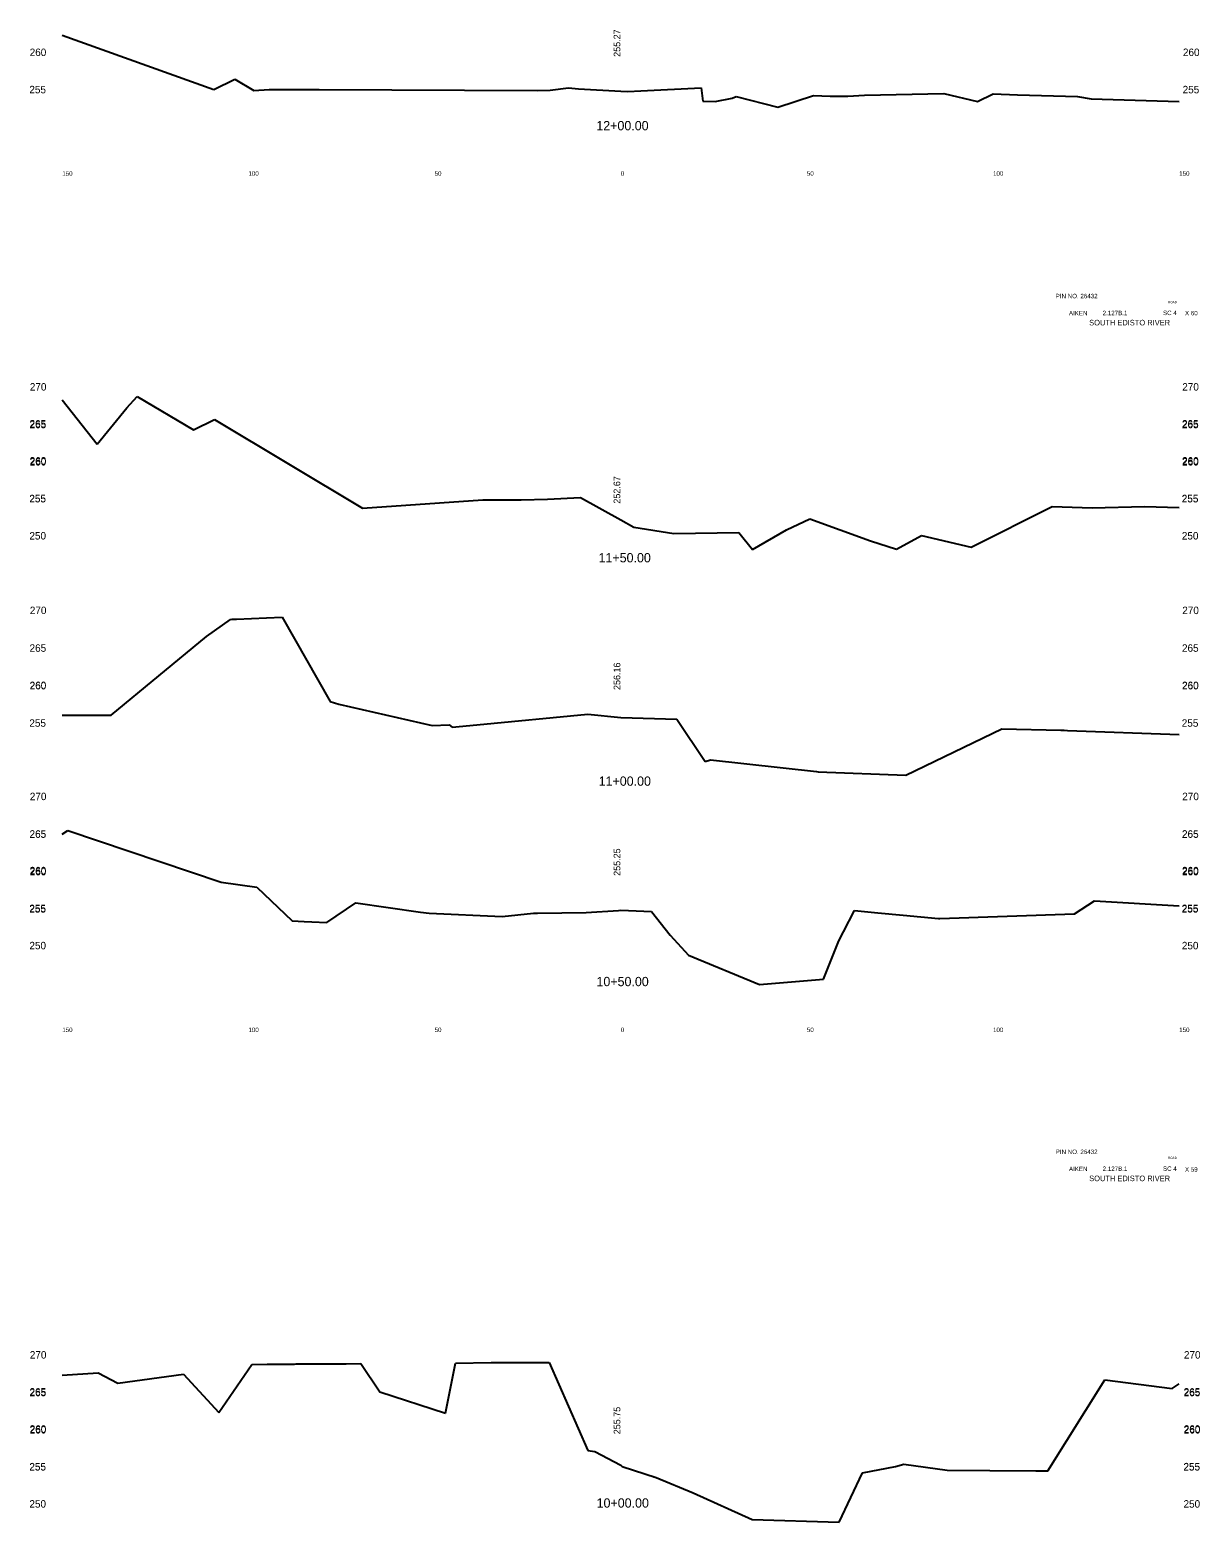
# Model space of a CAD drawing. Extents: x 557 to 872, y 628 to 2216.
# Drawn here: x 557.8 to 872.2, y 1426.2 to 1827 of the extents above; entities that cross this region are included whole.
import ezdxf

# ---------------------------------------------------------------- set-up
doc = ezdxf.new("R2010")
doc.units = 0
for name, color, linetype in [('Level 1', 7, 'Continuous'), ('Level 10', 7, 'Continuous'), ('Level 13', 7, 'Continuous'), ('Level 3', 7, 'Continuous'), ('Level 60', 7, 'Continuous')]:
    doc.layers.add(name, color=color, linetype=linetype)

msp = doc.modelspace()

# ---------------------------------------------------------------- linework, layer by layer
at = {"layer": 'Level 60'}
for p, q in [((566.54, 1825.54), (607.23, 1810.95)), ((607.23, 1810.95), (612.84, 1813.76)), ((612.84, 1813.76), (617.95, 1810.7)), ((617.95, 1810.7), (622.1, 1810.99)), ((622.1, 1810.99), (635.53, 1810.96)), ((635.53, 1810.96), (694.09, 1810.69)), ((694.09, 1810.69), (697.55, 1810.81)), ((697.55, 1810.81), (702.52, 1811.44)), ((702.52, 1811.44), (705.21, 1811.16)), ((705.21, 1811.16), (716.54, 1810.55)), ((716.54, 1810.55), (718.47, 1810.44)), ((718.47, 1810.44), (721.9, 1810.57)), ((721.9, 1810.57), (738.11, 1811.4)), ((738.11, 1811.4), (738.59, 1807.82)), ((738.59, 1807.82), (741.89, 1807.7)), ((741.89, 1807.7), (746.47, 1808.64)), ((746.47, 1808.64), (747.56, 1809.06)), ((747.56, 1809.06), (758.71, 1806.2)), ((758.71, 1806.2), (768.31, 1809.34)), ((768.31, 1809.34), (772.82, 1809.14)), ((772.82, 1809.14), (777.52, 1809.14)), ((777.52, 1809.14), (782.05, 1809.46)), ((782.05, 1809.46), (803.35, 1809.88)), ((803.35, 1809.88), (812.35, 1807.77)), ((812.35, 1807.77), (816.59, 1809.81)), ((816.59, 1809.81), (823.11, 1809.54)), ((823.11, 1809.54), (839.22, 1809.07)), ((839.22, 1809.07), (842.87, 1808.44)), ((842.87, 1808.44), (866.54, 1807.73)), ((566.54, 1727.6), (575.88, 1715.67)), ((583.88, 1725.47), (586.62, 1728.46)), ((586.62, 1728.46), (601.82, 1719.56)), ((575.88, 1715.67), (583.88, 1725.47)), ((601.82, 1719.56), (607.39, 1722.35)), ((607.39, 1722.35), (647.2, 1698.52)), ((647.2, 1698.52), (679.53, 1700.78)), ((679.53, 1700.78), (681.44, 1700.77)), ((681.44, 1700.77), (689.78, 1700.73)), ((689.78, 1700.73), (696.88, 1700.97)), ((696.88, 1700.97), (705.72, 1701.34)), ((705.72, 1701.34), (716.54, 1695.34)), ((761.07, 1692.69), (767.33, 1695.61)), ((767.33, 1695.61), (783.64, 1689.76)), ((810.64, 1688.07), (832.45, 1698.95)), ((832.45, 1698.95), (843.18, 1698.62)), ((843.18, 1698.62), (857.19, 1698.98)), ((857.19, 1698.98), (866.54, 1698.7)), ((716.54, 1695.34), (720.09, 1693.37)), ((720.09, 1693.37), (730.76, 1691.69)), ((730.76, 1691.69), (748.3, 1691.93)), ((748.3, 1691.93), (751.94, 1687.43)), ((751.94, 1687.43), (761.07, 1692.69)), ((783.64, 1689.76), (790.62, 1687.5)), ((790.62, 1687.5), (797.33, 1691.17)), ((797.33, 1691.17), (810.64, 1688.07)), ((605.24, 1664.07), (611.69, 1668.61)), ((611.69, 1668.61), (612.14, 1668.69)), ((612.14, 1668.69), (613.33, 1668.69)), ((613.33, 1668.69), (621.42, 1669.05)), ((621.42, 1669.05), (625.63, 1669.21)), ((625.63, 1669.21), (638.49, 1646.61)), ((579.62, 1642.92), (605.24, 1664.07)), ((638.49, 1646.61), (640.77, 1645.9)), ((640.77, 1645.9), (665.85, 1640.12)), ((566.54, 1642.87), (579.62, 1642.92)), ((665.85, 1640.12), (670.42, 1640.34)), ((670.42, 1640.34), (671.26, 1639.65)), ((671.26, 1639.65), (677.89, 1640.29)), ((677.89, 1640.29), (707.74, 1643.14)), ((707.74, 1643.14), (716.54, 1642.31)), ((716.54, 1642.31), (731.6, 1641.84)), ((731.6, 1641.84), (739.17, 1630.44)), ((793.13, 1626.81), (818.87, 1639.24)), ((818.87, 1639.24), (834.73, 1638.88)), ((834.73, 1638.88), (835.62, 1638.88)), ((835.62, 1638.88), (836.57, 1638.8)), ((836.57, 1638.8), (866.54, 1637.74)), ((739.17, 1630.44), (740.69, 1630.88)), ((740.69, 1630.88), (769.15, 1627.74)), ((769.15, 1627.74), (769.56, 1627.72)), ((769.56, 1627.72), (793.13, 1626.81)), ((566.54, 1610.96), (568.01, 1611.92)), ((568.01, 1611.92), (609.22, 1598.09)), ((609.22, 1598.09), (618.75, 1596.75)), ((618.75, 1596.75), (628.25, 1587.63)), ((637.6, 1587.24), (645.36, 1592.47)), ((645.36, 1592.47), (662.71, 1590.04)), ((838.4, 1589.53), (843.77, 1593.08)), ((843.77, 1593.08), (866.54, 1591.71)), ((628.25, 1587.63), (631.49, 1587.45)), ((631.49, 1587.45), (633.55, 1587.44)), ((633.55, 1587.44), (637.6, 1587.24)), ((662.71, 1590.04), (665.06, 1589.69)), ((665.06, 1589.69), (684.73, 1588.8)), ((684.73, 1588.8), (693.06, 1589.74)), ((693.06, 1589.74), (694.22, 1589.77)), ((694.22, 1589.77), (707.28, 1589.94)), ((707.28, 1589.94), (715.97, 1590.46)), ((715.97, 1590.46), (716.58, 1590.5)), ((716.58, 1590.5), (724.84, 1590.2)), ((724.84, 1590.2), (729.83, 1583.86)), ((776.36, 1584.74), (779.35, 1590.42)), ((779.35, 1590.42), (785.61, 1589.81)), ((785.61, 1589.81), (792.38, 1589.17)), ((792.38, 1589.17), (801.92, 1588.3)), ((801.92, 1588.3), (802.29, 1588.31)), ((802.29, 1588.31), (838.4, 1589.53)), ((729.83, 1583.86), (734.72, 1578.48)), ((775.09, 1582.29), (776.36, 1584.74)), ((770.99, 1571.98), (775.09, 1582.29)), ((734.72, 1578.48), (753.82, 1570.6)), ((753.82, 1570.6), (770.99, 1571.98)), ((608.54, 1455.64), (617.46, 1468.53)), ((617.46, 1468.53), (621.57, 1468.59)), ((621.57, 1468.59), (622.02, 1468.62)), ((622.02, 1468.62), (628.9, 1468.64)), ((628.9, 1468.64), (629.32, 1468.72)), ((629.32, 1468.72), (642.8, 1468.72)), ((642.8, 1468.72), (646.73, 1468.74)), ((646.73, 1468.74), (651.87, 1461.14)), ((669.49, 1455.46), (672.12, 1468.91)), ((672.12, 1468.91), (681.77, 1469.03)), ((681.77, 1469.03), (697.28, 1469.09)), ((697.28, 1469.09), (707.7, 1445.42)), ((566.54, 1465.61), (576.16, 1466.26)), ((576.16, 1466.26), (581.42, 1463.49)), ((581.42, 1463.49), (599.09, 1465.95)), ((599.09, 1465.95), (608.54, 1455.64)), ((831.3, 1439.95), (846.6, 1464.39)), ((846.6, 1464.39), (864.67, 1462.05)), ((864.67, 1462.05), (866.54, 1463.29)), ((651.87, 1461.14), (669.49, 1455.46)), ((707.7, 1445.42), (709.6, 1445.14)), ((709.6, 1445.14), (716.6, 1441.46)), ((716.6, 1441.46), (716.91, 1441.14)), ((716.91, 1441.14), (726.07, 1438.15)), ((775.23, 1426.17), (781.45, 1439.44)), ((781.45, 1439.44), (790.34, 1441.12)), ((790.34, 1441.12), (792.56, 1441.7)), ((792.56, 1441.7), (792.66, 1441.56)), ((792.56, 1441.7), (804.26, 1440.16)), ((804.26, 1440.16), (815.68, 1440.04)), ((815.68, 1440.04), (828.02, 1439.92)), ((828.02, 1439.92), (831.3, 1439.95)), ((725.46, 1438.38), (726.07, 1438.15)), ((726.07, 1438.15), (735.95, 1434.02)), ((735.95, 1434.02), (751.85, 1426.9)), ((751.85, 1426.9), (775.23, 1426.17))]:
    msp.add_line(p, q, dxfattribs=at)

# ---------------------------------------------------------------- texts
at = {"layer": 'Level 1'}
for s, height, p in [('12+00.00', 2.5, (709.98, 1800)), ('PIN NO. 26432', 1.2, (833.38, 1754.88)), ('SC 4', 1.2, (862.2, 1750.36)), ('ROAD', 0.6, (863.53, 1753.55)), ('AIKEN', 1.2, (836.93, 1750.29)), ('SOUTH EDISTO RIVER', 1.5, (842.36, 1747.59)), (' 2.127B.1', 1.2, (845.53, 1750.34)), ('X 60', 1.2, (868.1, 1750.3)), ('11+50.00', 2.5, (710.58, 1683.95)), ('11+00.00', 2.5, (710.61, 1623.95)), ('10+50.00', 2.5, (710.02, 1570.12)), ('PIN NO. 26432', 1.2, (833.38, 1525.04)), ('ROAD', 0.6, (863.53, 1523.71)), ('AIKEN', 1.2, (836.93, 1520.44)), ('SOUTH EDISTO RIVER', 1.5, (842.36, 1517.75)), (' 2.127B.1', 1.2, (845.53, 1520.49)), ('SC 4', 1.2, (862.2, 1520.51)), ('X 59', 1.2, (868.1, 1520.31)), ('10+00.00', 2.5, (710.06, 1430.07))]:
    msp.add_text(s, height=height, dxfattribs=at).set_placement(p)
at = {"layer": 'Level 10'}
for s, p in [('255.27', (716.43, 1819.74)), ('252.67', (716.41, 1699.73)), ('256.16', (716.43, 1649.68)), ('255.25', (716.43, 1599.76)), ('255.75', (716.43, 1449.78))]:
    msp.add_text(s, height=1.8, rotation=90, dxfattribs=at).set_placement(p)
at = {"layer": 'Level 13'}
for s, p in [('150', (566.54, 1787.8)), ('100', (616.54, 1787.8)), ('50', (666.54, 1787.8)), ('0', (716.54, 1787.8)), ('50', (766.54, 1787.8)), ('100', (816.54, 1787.8)), ('150', (866.54, 1787.8)), ('150', (566.54, 1557.8)), ('100', (616.54, 1557.8)), ('50', (666.54, 1557.8)), ('0', (716.54, 1557.8)), ('50', (766.54, 1557.8)), ('100', (816.54, 1557.8)), ('150', (866.54, 1557.8))]:
    msp.add_text(s, height=1.2, dxfattribs=at).set_placement(p)
at = {"layer": 'Level 3'}
for s, p in [(' 260', (557.03, 1819.95)), (' 260', (866.8, 1819.95)), (' 255', (556.94, 1809.94)), (' 255', (866.72, 1809.94)), (' 270', (557.07, 1730.09)), (' 270', (866.62, 1730.09)), (' 265', (557, 1720.19)), (' 265', (557, 1719.97)), (' 265', (866.55, 1720.19)), (' 265', (866.55, 1719.97)), (' 260', (557.03, 1710.23)), (' 260', (557.03, 1710.06)), (' 260', (557.03, 1709.95)), (' 260', (866.57, 1710.23)), (' 260', (866.57, 1710.06)), (' 260', (866.57, 1709.95)), (' 255', (556.94, 1700.11)), (' 255', (556.94, 1700.05)), (' 255', (866.49, 1700.11)), (' 255', (866.49, 1700.05)), (' 250', (556.96, 1690.09)), (' 250', (866.51, 1690.09)), (' 270', (557.07, 1670.06)), (' 270', (866.62, 1670.06)), (' 265', (557, 1659.94)), (' 265', (557, 1659.94)), (' 265', (866.55, 1659.94)), (' 265', (866.55, 1659.94)), (' 260', (557.03, 1649.93)), (' 260', (557.03, 1649.82)), (' 260', (866.57, 1649.93)), (' 260', (866.57, 1649.82)), (' 255', (556.94, 1639.8)), (' 255', (866.49, 1639.8)), (' 270', (557.07, 1620.08)), (' 270', (866.62, 1620.08)), (' 265', (557, 1610.01)), (' 265', (557, 1609.96)), (' 265', (866.55, 1610.01)), (' 265', (866.55, 1609.96)), (' 260', (557.03, 1600.17)), (' 260', (557.03, 1599.95)), (' 260', (557.03, 1599.89)), (' 260', (866.57, 1600.17)), (' 260', (866.57, 1599.95)), (' 260', (866.57, 1599.89)), (' 255', (556.94, 1590.04)), (' 255', (556.94, 1589.88)), (' 255', (866.49, 1590.04)), (' 255', (866.49, 1589.88)), (' 250', (556.96, 1580.03)), (' 250', (866.51, 1580.03)), (' 270', (557.07, 1470.1)), (' 270', (867.07, 1470.1)), (' 265', (557, 1460.16)), (' 265', (557, 1459.97)), (' 265', (867, 1460.16)), (' 265', (867, 1459.97)), (' 260', (557.03, 1450.2)), (' 260', (557.03, 1450.04)), (' 260', (557.03, 1449.96)), (' 260', (867.02, 1450.2)), (' 260', (867.02, 1450.04)), (' 260', (867.02, 1449.96)), (' 255', (556.94, 1440.08)), (' 255', (556.94, 1440.02)), (' 255', (866.94, 1440.08)), (' 255', (866.94, 1440.02)), (' 250', (556.96, 1430.07)), (' 250', (866.96, 1430.07))]:
    msp.add_text(s, height=2, dxfattribs=at).set_placement(p)

doc.saveas('drawing.dxf')
